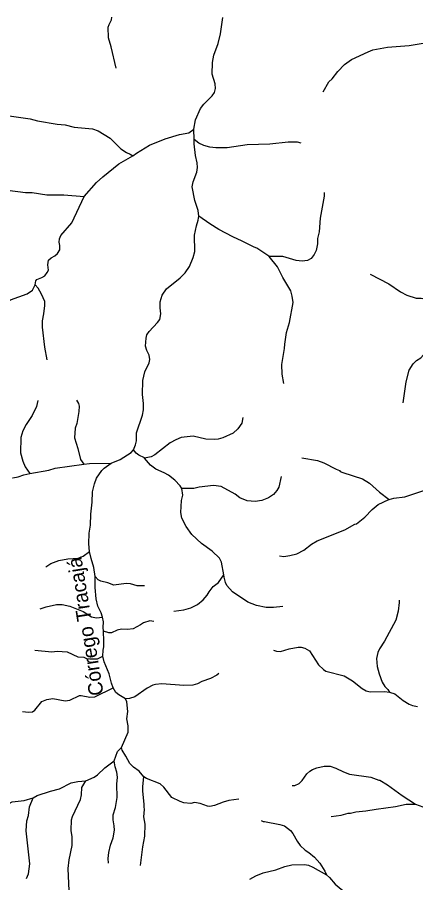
# Model space of a CAD drawing. Extents: x 500 to 555.2, y 9115.7 to 9171.
# Drawn here: x 513.43 to 517.83, y 9161.41 to 9170.97 of the extents above; entities that cross this region are included whole.
import ezdxf
from ezdxf.enums import TextEntityAlignment as Align

# ---------------------------------------------------------------- set-up
doc = ezdxf.new("R2010")
doc.units = 0
doc.header["$LTSCALE"] = 0.064
doc.layers.add('61', color=7, linetype='Continuous')
doc.layers.add('7', color=7, linetype='Continuous', lineweight=25)

msp = doc.modelspace()

# ---------------------------------------------------------------- linework, layer by layer
at = {"layer": '7'}
for points in [[(514.5203, 9170.4089), (514.4641, 9170.6469), (514.4343, 9170.7471), (514.433, 9170.8634), (514.4407, 9170.8936), (514.4668, 9170.9461), (514.4732, 9170.9722)], [(515.3786, 9169.7354), (515.3966, 9169.8384), (515.4506, 9169.9645), (515.488, 9170.0123), (515.5808, 9170.1053), (515.6034, 9170.141), (515.6149, 9170.1845), (515.612, 9170.2375), (515.5808, 9170.3437), (515.5841, 9170.4737), (515.5989, 9170.553), (515.644, 9170.6818), (515.6709, 9170.7886), (515.6962, 9170.9718)], [(516.8033, 9170.148), (516.8673, 9170.258), (516.9037, 9170.293), (516.9665, 9170.3738), (517.0413, 9170.4517), (517.1167, 9170.5056), (517.299, 9170.5926), (517.354, 9170.612), (517.5147, 9170.6415), (517.7549, 9170.6609), (518.0643, 9170.7134), (518.3949, 9170.83), (518.4531, 9170.8432), (518.484, 9170.8424)], [(513.3376, 9169.8858), (513.5721, 9169.8525), (513.6502, 9169.8298), (513.8682, 9169.7938), (513.9561, 9169.7858), (514.0566, 9169.7607), (514.2571, 9169.7394), (514.3221, 9169.7166), (514.4519, 9169.6383), (514.57, 9169.5204), (514.633, 9169.4778), (514.6743, 9169.4618), (514.7045, 9169.4415)], [(514.7045, 9169.4415), (514.7442, 9169.4728), (514.8865, 9169.5603), (515.0591, 9169.6316), (515.2189, 9169.6781), (515.3205, 9169.6971), (515.3786, 9169.7354)], [(515.4307, 9168.7762), (515.4249, 9168.8376), (515.3863, 9168.9494), (515.3579, 9169.0991), (515.3691, 9169.1549), (515.4105, 9169.2618), (515.4168, 9169.3123), (515.4135, 9169.3648), (515.3939, 9169.4442), (515.3791, 9169.5748), (515.379, 9169.6226), (515.3786, 9169.7354)], [(516.5627, 9169.582), (516.5207, 9169.5918), (516.4163, 9169.5918), (516.2157, 9169.5705), (515.9663, 9169.5622), (515.7459, 9169.5311), (515.6212, 9169.5312), (515.5547, 9169.5396), (515.4865, 9169.5573), (515.4316, 9169.582), (515.379, 9169.6226)], [(514.1665, 9168.9933), (514.3035, 9169.1478), (514.3709, 9169.2104), (514.5491, 9169.3539), (514.7045, 9169.4415)], [(512.6145, 9169.0203), (512.6593, 9169.023), (512.8477, 9169.0064), (512.9744, 9169.0096), (513.2073, 9169.0587), (513.3221, 9169.062), (513.5178, 9169.0391), (513.5938, 9169.0374), (513.7551, 9169.0133), (513.9429, 9169.0111), (514.1665, 9168.9933)], [(513.627, 9168.0161), (513.6298, 9168.0412), (513.6324, 9168.0617), (513.6427, 9168.0746), (513.6994, 9168.0992), (513.7308, 9168.118), (513.7596, 9168.1527), (513.7714, 9168.1801), (513.7652, 9168.2385), (513.7716, 9168.2888), (513.8028, 9168.3156), (513.8437, 9168.337), (513.8737, 9168.3622), (513.8974, 9168.4048), (513.8994, 9168.4501), (513.8915, 9168.4889), (513.8929, 9168.5273), (513.9093, 9168.5633), (514.031, 9168.7034), (514.1665, 9168.9933)], [(516.8159, 9169.0388), (516.814, 9168.9983), (516.7715, 9168.754), (516.7584, 9168.6038), (516.7421, 9168.5283), (516.7404, 9168.4693), (516.727, 9168.3972), (516.7044, 9168.3534), (516.6732, 9168.3091), (516.6317, 9168.286), (516.572, 9168.2796), (516.5076, 9168.2878), (516.3594, 9168.3305), (516.2067, 9168.3322)], [(515.0762, 9167.975), (515.2253, 9168.0947), (515.281, 9168.1489), (515.3278, 9168.22), (515.371, 9168.3196), (515.3873, 9168.3852), (515.3826, 9168.5666), (515.4065, 9168.6693), (515.4244, 9168.7309), (515.4307, 9168.7762)], [(516.2067, 9168.3322), (516.2063, 9168.3326), (516.0728, 9168.4214), (516.0418, 9168.4322), (515.9112, 9168.5007), (515.8072, 9168.5477), (515.652, 9168.6302), (515.5541, 9168.6899), (515.4307, 9168.7762)], [(516.3708, 9166.9263), (516.3504, 9167.0303), (516.347, 9167.1389), (516.378, 9167.3157), (516.3799, 9167.3636), (516.3995, 9167.4899), (516.4321, 9167.6005), (516.4713, 9167.8236), (516.463, 9167.8907), (516.4486, 9167.9509), (516.3603, 9168.0986), (516.3009, 9168.2172), (516.2067, 9168.3322)], [(517.3212, 9168.1359), (517.5273, 9168.0288), (517.6571, 9167.942), (517.7268, 9167.9028), (517.8315, 9167.8713), (517.8848, 9167.8695), (517.974, 9167.8513), (518.1014, 9167.7604), (518.1858, 9167.7207), (518.2528, 9167.7055), (518.3817, 9167.6896)], [(512.9775, 9167.1598), (513.0661, 9167.3119), (513.1231, 9167.4255), (513.1565, 9167.5059), (513.2029, 9167.6457), (513.2254, 9167.6923), (513.3145, 9167.8258), (513.3534, 9167.8507), (513.5361, 9167.9175), (513.5965, 9167.9571), (513.627, 9168.0161)], [(513.757, 9167.1888), (513.7314, 9167.3308), (513.7078, 9167.5502), (513.7061, 9167.6181), (513.7223, 9167.6962), (513.7322, 9167.7875), (513.7306, 9167.8328), (513.6964, 9167.9148), (513.6604, 9167.9813), (513.627, 9168.0161)], [(514.7102, 9166.1955), (514.7328, 9166.2494), (514.7424, 9166.2942), (514.743, 9166.3823), (514.8115, 9166.577), (514.8207, 9166.638), (514.8213, 9166.7082), (514.8116, 9166.8051), (514.8135, 9166.9623), (514.8352, 9167.0564), (514.882, 9167.1565), (514.8901, 9167.1937), (514.8851, 9167.2402), (514.8586, 9167.2936), (514.8428, 9167.3404), (514.8492, 9167.4293), (514.8587, 9167.4645), (514.8841, 9167.5026), (514.9751, 9167.6), (515.0019, 9167.6357), (515.0132, 9167.6989), (515.0034, 9167.7652), (515.0035, 9167.8301), (515.0256, 9167.9037), (515.0762, 9167.975)], [(517.6871, 9166.7128), (517.7201, 9166.9464), (517.7528, 9167.0762), (517.7981, 9167.1441), (517.8341, 9167.18), (517.8821, 9167.2118), (517.9109, 9167.2456), (517.9626, 9167.3379), (517.9872, 9167.3692), (518.0382, 9167.4157), (518.1286, 9167.514), (518.1515, 9167.538), (518.2279, 9167.5888), (518.3104, 9167.6345), (518.3817, 9167.6896)], [(513.6549, 9166.7414), (513.6402, 9166.6722), (513.5931, 9166.5743), (513.5259, 9166.4757), (513.4897, 9166.4068), (513.4679, 9166.3321), (513.4628, 9166.1623), (513.4897, 9166.0711), (513.5154, 9166.0068), (513.5685, 9165.932)], [(514.0826, 9166.7425), (514.1029, 9166.7055), (514.1118, 9166.6774), (514.1078, 9166.619), (514.0848, 9166.4852), (514.0684, 9166.4353), (514.0585, 9166.3289), (514.0963, 9166.2087), (514.1278, 9166.0884), (514.1628, 9166.0352)], [(515.9186, 9166.5535), (515.9051, 9166.4896), (515.8621, 9166.4271), (515.8126, 9166.3789), (515.6954, 9166.3286), (515.6448, 9166.3129), (515.6067, 9166.308), (515.5076, 9166.3128), (515.3687, 9166.3456), (515.2386, 9166.331), (515.1776, 9166.3073), (515.1142, 9166.2724), (514.945, 9166.1391), (514.9057, 9166.1191), (514.834, 9166.1049)], [(514.4639, 9166.0492), (514.5655, 9166.0882), (514.6841, 9166.1665), (514.7102, 9166.1955)], [(514.834, 9166.1049), (514.8327, 9166.1064), (514.77, 9166.1356), (514.7388, 9166.1599), (514.7102, 9166.1955)], [(513.5685, 9165.932), (513.7756, 9165.9702), (513.8477, 9165.9931), (514.1628, 9166.0352)], [(514.1628, 9166.0352), (514.2258, 9166.0436), (514.4639, 9166.0492)], [(514.2261, 9165.0705), (514.2261, 9165.0706), (514.2178, 9165.1571), (514.2227, 9165.2739), (514.2374, 9165.3632), (514.2407, 9165.4839), (514.2555, 9165.6157), (514.26, 9165.7312), (514.2813, 9165.821), (514.3031, 9165.8815), (514.3609, 9165.9672), (514.3874, 9165.9935), (514.4639, 9166.0492)], [(515.2449, 9165.7663), (515.2248, 9165.798), (515.1653, 9165.8606), (515.0958, 9165.917), (515.051, 9165.9421), (514.9583, 9165.9819), (514.899, 9166.027), (514.834, 9166.1049)], [(516.5678, 9166.1067), (516.7433, 9166.0767), (516.8105, 9166.0532), (516.9486, 9165.9799), (516.986, 9165.9667), (516.9929, 9165.9572), (517.0204, 9165.9433), (517.2385, 9165.8767), (517.3141, 9165.8277), (517.4268, 9165.7266), (517.5309, 9165.6452)], [(513.3767, 9165.8854), (513.3797, 9165.8851), (513.4375, 9165.8976), (513.4994, 9165.9192), (513.5685, 9165.932)], [(516.3416, 9165.8992), (516.3132, 9165.7846), (516.292, 9165.746), (516.2564, 9165.7024), (516.2012, 9165.6653), (516.1266, 9165.6366), (516.0555, 9165.6256), (515.9636, 9165.6306), (515.8845, 9165.665), (515.8318, 9165.7059), (515.6779, 9165.7895), (515.5931, 9165.8026), (515.4363, 9165.7833), (515.3752, 9165.7666), (515.2449, 9165.7663)], [(515.7074, 9164.8137), (515.6838, 9164.9537), (515.6598, 9165.0001), (515.5781, 9165.0756), (515.4611, 9165.1615), (515.3555, 9165.2619), (515.2914, 9165.3494), (515.2446, 9165.442), (515.2348, 9165.5042), (515.2412, 9165.6339), (515.2543, 9165.6946), (515.2449, 9165.7663)], [(517.5309, 9165.6452), (517.5841, 9165.6617), (517.7057, 9165.6767), (517.98, 9165.7681), (518.0796, 9165.7929)], [(516.3235, 9165.0248), (516.3704, 9165.0187), (516.436, 9165.027), (516.5146, 9165.0468), (516.5924, 9165.0872), (516.6739, 9165.1524), (516.738, 9165.1897), (517.0426, 9165.3129), (517.1553, 9165.3737), (517.1712, 9165.3778), (517.2632, 9165.4513), (517.3431, 9165.5358), (517.4122, 9165.5907), (517.5302, 9165.645), (517.5309, 9165.6452)], [(513.7445, 9164.9025), (513.7994, 9164.9383), (513.887, 9164.9746), (513.9854, 9164.9909), (514.1016, 9164.9988), (514.1565, 9165.021), (514.2261, 9165.0705)], [(514.2872, 9164.7948), (514.2733, 9164.8947), (514.2422, 9164.9965), (514.2261, 9165.0705)], [(514.3699, 9164.3479), (514.3544, 9164.394), (514.3159, 9164.4703), (514.2971, 9164.5489), (514.2867, 9164.6729), (514.2872, 9164.7948)], [(514.8332, 9164.6931), (514.7513, 9164.694), (514.6776, 9164.7134), (514.6284, 9164.7201), (514.4954, 9164.7005), (514.428, 9164.7246), (514.3491, 9164.7448), (514.3203, 9164.7603), (514.2872, 9164.7948)], [(515.1552, 9164.413), (515.2662, 9164.4296), (515.3431, 9164.4516), (515.4173, 9164.4882), (515.4804, 9164.5377), (515.523, 9164.5885), (515.5455, 9164.6276), (515.5915, 9164.6846), (515.6485, 9164.7318), (515.7074, 9164.8137)], [(516.3576, 9164.4643), (516.2556, 9164.4545), (516.1762, 9164.4545), (516.0687, 9164.475), (515.9731, 9164.5133), (515.8049, 9164.626), (515.7416, 9164.6956), (515.7268, 9164.7289), (515.7117, 9164.7883), (515.7074, 9164.8137)], [(517.6414, 9164.5363), (517.6441, 9164.5087), (517.6304, 9164.4117), (517.6066, 9164.3139), (517.4816, 9164.0833), (517.4247, 9163.9956), (517.4063, 9163.9554), (517.3918, 9163.8912), (517.4015, 9163.8022), (517.4211, 9163.7202), (517.4548, 9163.63), (517.4832, 9163.5824), (517.5186, 9163.55), (517.5378, 9163.52)], [(513.6813, 9164.4388), (513.7458, 9164.4607), (513.8596, 9164.4853), (513.9253, 9164.4856), (514.0073, 9164.4677), (514.1553, 9164.4083), (514.2462, 9164.351), (514.3024, 9164.3396), (514.3699, 9164.3479)], [(514.3782, 9164.1926), (514.3756, 9164.2335), (514.3784, 9164.297), (514.3699, 9164.3479)], [(514.9344, 9164.2988), (514.8915, 9164.3068), (514.8209, 9164.2851), (514.7897, 9164.2624), (514.7086, 9164.2196), (514.6455, 9164.2117), (514.5779, 9164.2131), (514.5316, 9164.2034), (514.4677, 9164.1726), (514.4384, 9164.1729), (514.3782, 9164.1926)], [(514.3732, 9163.9158), (514.3744, 9163.9843), (514.3817, 9164.0188), (514.3851, 9164.0836), (514.3782, 9164.1926)], [(513.6231, 9163.9841), (513.8096, 9163.9624), (513.8676, 9163.9722), (513.9771, 9163.9657), (514.0967, 9163.9103), (514.1642, 9163.9049), (514.1905, 9163.8922), (514.2296, 9163.887), (514.3128, 9163.8887), (514.3732, 9163.9158)], [(516.2567, 9163.9822), (516.2906, 9163.9707), (516.3342, 9163.9673), (516.4288, 9163.9967), (516.5268, 9164.0163), (516.5601, 9164.0148), (516.6, 9164.0047), (516.6523, 9163.975), (516.7525, 9163.8208), (516.8084, 9163.7681), (516.8328, 9163.7525), (517.0357, 9163.6981), (517.1264, 9163.6438), (517.2353, 9163.5597), (517.2781, 9163.5338), (517.3239, 9163.5228), (517.4826, 9163.526), (517.5378, 9163.52)], [(514.4877, 9163.5658), (514.4683, 9163.6179), (514.4413, 9163.7214), (514.387, 9163.8535), (514.3732, 9163.9158)], [(515.6526, 9163.7233), (515.6307, 9163.7049), (515.559, 9163.6701), (515.4656, 9163.6364), (515.4163, 9163.6102), (515.3671, 9163.5969), (515.2675, 9163.5917), (515.0221, 9163.6112), (514.9545, 9163.6043), (514.9226, 9163.5946), (514.8616, 9163.5623), (514.7245, 9163.4654), (514.6678, 9163.4474), (514.6231, 9163.4466)], [(513.4869, 9163.3043), (513.5506, 9163.2964), (513.5954, 9163.3013), (513.6229, 9163.3215), (513.7, 9163.4151), (513.754, 9163.4387), (513.8214, 9163.4488), (513.9573, 9163.4212), (514.0074, 9163.4286), (514.1141, 9163.4801), (514.1341, 9163.4814), (514.2283, 9163.4621), (514.2835, 9163.4675), (514.4877, 9163.5658)], [(514.6231, 9163.4466), (514.5472, 9163.4875), (514.516, 9163.5148), (514.4877, 9163.5658)], [(514.5776, 9162.9066), (514.6518, 9163.078), (514.6506, 9163.1462), (514.6378, 9163.2236), (514.6473, 9163.3059), (514.6377, 9163.412), (514.6231, 9163.4466)], [(517.5378, 9163.52), (517.596, 9163.499), (517.6873, 9163.4278), (517.7531, 9163.3871), (517.7893, 9163.3723), (517.8442, 9163.3618)], [(514.4987, 9162.7601), (514.5354, 9162.8652), (514.5776, 9162.9066)], [(514.8241, 9162.5844), (514.7749, 9162.6454), (514.7099, 9162.6891), (514.6701, 9162.731), (514.6281, 9162.8135), (514.5847, 9162.8788), (514.5776, 9162.9066)], [(514.1863, 9162.5385), (514.2774, 9162.5816), (514.3133, 9162.6047), (514.3927, 9162.684), (514.4987, 9162.7601)], [(514.4353, 9161.6306), (514.431, 9161.6829), (514.4376, 9161.7479), (514.4557, 9161.8292), (514.4865, 9161.9115), (514.5015, 9161.994), (514.4983, 9162.0427), (514.4852, 9162.1088), (514.4855, 9162.1626), (514.5128, 9162.2467), (514.5292, 9162.3568), (514.5277, 9162.5015), (514.5326, 9162.5818), (514.5277, 9162.637), (514.51, 9162.6955), (514.4987, 9162.7601)], [(516.4604, 9162.4875), (516.4911, 9162.4895), (516.5383, 9162.509), (516.5728, 9162.5414), (516.6234, 9162.615), (516.6564, 9162.6464), (516.6858, 9162.6645), (516.7327, 9162.6826), (516.8147, 9162.7023), (516.8829, 9162.7007), (516.9453, 9162.6804), (517.0277, 9162.6403), (517.0964, 9162.6141), (517.3316, 9162.581), (517.4202, 9162.546), (517.4308, 9162.5464), (517.5153, 9162.4938), (517.6771, 9162.3779), (517.8219, 9162.2831)], [(513.6045, 9162.3527), (513.6495, 9162.3777), (513.7945, 9162.4254), (513.893, 9162.45), (514.0236, 9162.5169), (514.0972, 9162.5336), (514.1859, 9162.5383), (514.1863, 9162.5385)], [(513.9998, 9161.3235), (513.9898, 9161.5709), (514.0026, 9161.6679), (514.034, 9161.8262), (514.0339, 9161.9219), (514.0242, 9161.9895), (514.0274, 9162.1082), (514.0376, 9162.1455), (514.1244, 9162.3341), (514.1357, 9162.3844), (514.141, 9162.467), (514.1863, 9162.5385)], [(514.7887, 9161.6037), (514.813, 9161.8122), (514.8375, 9161.9272), (514.8393, 9162.0602), (514.8247, 9162.1404), (514.8312, 9162.223), (514.8268, 9162.2513), (514.8296, 9162.2827), (514.8133, 9162.4258), (514.8133, 9162.4775), (514.8241, 9162.5844)], [(515.8728, 9162.3353), (515.7644, 9162.3216), (515.6988, 9162.305), (515.6049, 9162.2661), (515.5535, 9162.2565), (515.5262, 9162.2599), (515.4474, 9162.2877), (515.3842, 9162.2986), (515.3436, 9162.2894), (515.2668, 9162.2951), (515.2244, 9162.3108), (515.1355, 9162.3557), (515.0451, 9162.4705), (515.0051, 9162.5056), (514.8534, 9162.5646), (514.8256, 9162.5826), (514.8241, 9162.5844)], [(513.2419, 9162.2751), (513.2421, 9162.2751), (513.3116, 9162.2762), (513.3728, 9162.3074), (513.5058, 9162.3238), (513.6045, 9162.3527)], [(513.5297, 9161.4617), (513.5513, 9161.512), (513.5664, 9161.6246), (513.5256, 9161.9874), (513.5323, 9162.099), (513.5516, 9162.1553), (513.5614, 9162.2519), (513.6045, 9162.3527)], [(516.8927, 9162.1448), (517.0023, 9162.1602), (517.079, 9162.1826), (517.104, 9162.1811), (517.1643, 9162.1957), (517.2759, 9162.2064), (517.3874, 9162.2269), (517.6015, 9162.2551), (517.7188, 9162.2827), (517.8219, 9162.2831)], [(517.8219, 9162.2831), (517.9052, 9162.2516), (517.9648, 9162.2416), (518.1801, 9162.227), (518.3119, 9162.1973), (518.4865, 9162.1424), (518.5475, 9162.1286), (518.6406, 9162.1303), (518.791, 9162.1727), (518.8834, 9162.171), (519.0014, 9162.1297), (519.1775, 9162.019), (519.2578, 9161.9782), (519.3152, 9161.9646), (519.3982, 9161.9588), (519.4648, 9161.9673)], [(516.1192, 9162.1016), (516.1433, 9162.089), (516.1569, 9162.0918), (516.3271, 9162.0579), (516.3764, 9162.0415), (516.4435, 9161.9923), (516.4686, 9161.959), (516.5166, 9161.8717), (516.5493, 9161.8255), (516.6072, 9161.773), (516.6471, 9161.7474), (516.7084, 9161.6947), (516.7667, 9161.6314), (516.8234, 9161.5427), (516.841, 9161.5015)], [(515.9934, 9161.4548), (516.0615, 9161.4904), (516.1422, 9161.5228), (516.2818, 9161.5578), (516.3802, 9161.5939), (516.4571, 9161.612), (516.5982, 9161.6166), (516.6415, 9161.6069), (516.6891, 9161.5866), (516.841, 9161.5015)], [(516.841, 9161.5015), (516.8746, 9161.4711), (516.9369, 9161.3974), (517.064, 9161.2928), (517.1179, 9161.2626), (517.2221, 9161.2428), (517.4321, 9161.2312), (517.4888, 9161.2162)]]:
    msp.add_lwpolyline(points, dxfattribs=at)

# ---------------------------------------------------------------- texts
at = {"layer": '61'}
msp.add_text('Córrego Tracajá', height=0.16, rotation=99.181, dxfattribs=at).set_placement((514.2591, 9164.2561), align=Align.CENTER)

doc.saveas('drawing.dxf')
